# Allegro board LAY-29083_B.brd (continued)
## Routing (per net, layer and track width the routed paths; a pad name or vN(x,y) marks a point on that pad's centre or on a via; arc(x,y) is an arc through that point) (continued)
MS1_LM1: length 316.8
  TOP w0.254: U9.47 v1(31.02,26.16) ; v1(37.86,26.67) 37.85,26.66 U9.15 ; U9.39 v1(31.02,30.16) ; U8.15 v1(62.33,26.74) ; U8.30 v1(58.32,32.7) ; U9.31 v1(33.36,32.62) ; U9.30 v1(33.86,31) ; U5.8 49.57,62.48 v1(49.82,62.74) ; v1(44.65,63.89) 44.91,63.64 U5.16 ; U8.39 v1(55.48,30.24) ; U8.47 v1(55.48,26.24) ; U8.31 v1(57.82,31.07)
  TOP w0.33: U6.4 v1(24.87,43.86)
  TOP w0.432: R32.2 v1(33.34,45.95)
  TOP w0.457: C18.2 v2(47.77,47.52) ; C17.2 v2(46.76,47.52) ; C10.2 v1(53.41,52.55)
  TOP w0.508: D17.A 75.23,29.75 v1(75.72,30.24) ; D17.A v1(73.18,29.75) ; D17.A v1(74.32,28.6) ; J5.A26 v1(59.5,74.57) ; v1(22.55,49) SW7.2 v1(24.12,50.41) ; J5.C49 v1(53.5,6.12) ; J5.A49 v1(36.5,74.57) ; C12.2 v2(50.57,49.56) ; J5.C6 v1(8.5,6.12) ; D20.A v1(15.77,16.03) ; D20.A v1(14.63,14.76) ; D20.A v1(13.48,16.03) ; C28.2 v1(16.71,28.44) ; C11.2 v2(50.57,50.57) ; C26.2 v1(66.07,25.83) ; C26.2 v1(68.45,25.83) ; C26.2 v1(67.26,23.65) ; Y5.4 27.03,32.69 26.52,33.2 v1(26.44,33.2) C23.2 25.65,33.33 25.06,33.92 24.34,33.92 23.43,33.01 23.43,29.41 24.53,28.3 v1(24.53,26.66) Y5.2 24.53,24.8 C29.2 ; C7.2 42.2,55.23 42.23,55.3 42.27,55.36 v1(42.55,55.64) ; J5.C5 v1(7.5,6.12) ; v1(36.82,56.07) SW6.2 v1(38.12,54.64) ; SW5.2 v1(71.44,62.64) ; J5.A65 v1(20.5,74.45) ; D11.A v1(15.64,50.82) ; D11.A v1(14.37,49.68) ; D11.A v1(13.36,50.82) ; v2(50.57,51.33) 50.82,51.59 C9.2 ; v1(73.43,64.42) D8.A v1(74.57,65.56) ; J5.C2 v1(4.5,6.12) ; D7.C v1(66.01,66.84) ; C14.2 v2(50.57,46.76) ; J5.A5 v1(82.5,74.57) ; C8.2 v1(73.23,52.26) ; C13.2 v2(50.57,47.78) ; R49.1 v1(27.77,20.5) ; U7.3 v1(5.29,39.93) ; C27.2 v1(41.48,25.73) ; C27.2 v1(43.87,25.73) ; C27.2 v1(42.67,23.55) ; J5.A31 v1(54.5,74.57) ; C25.2 v1(39.2,29.13) ; C16.2 45.74,47.14 46.12,47.52 v2(46.76,47.52) ; v1(85.5,6.12) J5.D81 ; v1(53.62,46) C15.1 ; R47.1 v1(52.24,20.57) ; C6.2 v1(16.71,62.98) ; C24.2 v1(63.82,29.21) ; J5.A2 v1(85.5,74.57) ; J5.C31 v1(35.5,6.12) ; C30.2 v1(73.23,17.59) ; J5.C26 v1(30.5,6.12) ; SW8.2 v1(39.77,48.79) ; C5.2 v1(62.43,64.38) ; J5.C65 v1(69.5,6.12) ; D5.C v1(66.01,68.83) D6.C ; J5.A6 v1(81.5,74.57) ; J5.B81 v1(4.5,74.57)
  L5_GND w0.381: 64.92,17.78 JP7.1 ; JP7.1 66.8,17.78 ; JP7.1 65.86,16.84 ; JP7.1 65.86,18.72 ; J24.3 83.22,26.81 ; J24.3 82.11,27.92 ; J24.3 82.11,25.71 ; J24.3 81,26.81 ; J17.2 82.29,41.07 ; J17.2 81.29,39.56 ; J17.2 82.29,38.04 ; J17.2 83.3,39.56 ; J11.3 8.94,53.75 ; J11.3 7.83,54.86 ; J11.3 7.83,52.65 ; J11.3 6.73,53.75 ; 82.11,59.56 J9.4 ; J9.4 83.21,60.67 ; J9.4 84.32,59.56 ; J9.4 83.21,58.46 ; J16.3 34.67,48.51 ; J16.3 34.67,46.63 ; J16.3 33.73,47.57 ; J16.3 35.61,47.57 ; JP9.1 69.67,12.5 ; JP9.1 70.74,11.43 ; JP9.1 68.6,11.43 ; JP9.1 69.67,10.36 ; 7.83,18.11 J23.3 ; J23.3 8.94,19.21 ; J23.3 6.73,19.21 ; J23.3 7.83,20.32 ; 82.12,10.69 JP11.1 ; JP11.1 84.15,10.69 ; JP11.1 83.13,11.71 ; JP11.1 83.13,9.68 ; J17.3 79.29,45.26 ; J17.3 80.8,44.26 ; J17.3 77.78,44.26 ; J17.3 79.29,43.25 ; 45.21,10.29 JP10.1 ; JP10.1 45.21,12.42 ; JP10.1 44.14,11.35 ; JP10.1 46.28,11.35 ; JP8.1 41.4,18.64 ; JP8.1 42.34,17.7 ; JP8.1 41.4,16.76 ; JP8.1 40.46,17.7 ; 49.63,39.7 J53.3 49.63,39.02 ; JP5.1 80.41,69.88 ; JP5.1 79.4,68.86 ; JP5.1 79.4,70.89 ; JP5.1 78.38,69.88 ; J10.3 83.22,61.49 ; J10.3 81,61.49 ; J10.3 82.11,60.38 ; J10.3 82.11,62.59 ; JP6.1 58.67,57.3 ; JP6.1 56.79,57.3 ; JP6.1 57.73,56.36 ; JP6.1 57.73,58.24 ; 78.13,22.02 J22.5 ; J22.5 77.03,23.12 ; J22.5 78.13,24.23 ; J22.5 79.24,23.12 ; 66.14,53.37 J15.5 66.14,54.05 ; 49.63,38.43 J53.5 49.63,37.75 ; J22.4 83.21,26 ; J22.4 84.32,24.89 ; J22.4 83.21,23.79 ; J22.4 82.11,24.89 ; TP13.1 21.65,38.14 ; TP13.1 20.32,39.47 ; TP13.1 20.32,36.8 ; TP13.1 18.98,38.14 ; J25.4 7.83,21.13 ; J25.4 6.73,22.24 ; J25.4 5.62,21.13 ; J25.4 6.73,20.03 ; 66.14,52.78 J15.3 66.14,52.1 ; J25.5 12.91,22.9 ; J25.5 11.81,21.8 ; J25.5 10.7,22.9 ; J25.5 11.81,24.01 ; J12.5 11.81,58.55 ; J12.5 12.91,57.45 ; J12.5 11.81,56.34 ; J12.5 10.7,57.45 ; J9.5 78.13,58.9 ; J9.5 77.03,57.79 ; J9.5 78.13,56.69 ; J9.5 79.24,57.79 ; 6.73,54.57 J12.4 ; J12.4 5.62,55.68 ; J12.4 7.83,55.68 ; J12.4 6.73,56.78
  BOTTOM w0.254: U52.B2 v1(72.54,15.39) ; C65.2 62.09,26.97 v1(62.33,26.74) 62.34,26.75 C67.2 ; v2(46.76,47.52) 46.67,47.43 U50.23 ; U50.2 50.6,51.3 v2(50.57,51.33) ; U50.11 52.82,46.8 v1(53.11,46.51) 52.9,46.3 U50.12 ; C66.2 v1(37.86,26.67) C68.2 ; U53.B2 v1(73.18,11.61)
  BOTTOM w0.432: C52.2 v1(49.82,62.74) C53.2 ; C57.2 C56.2 v1(26.26,45.94) ; C50.2 v1(44.65,63.89) C51.2
  BOTTOM w0.457: C15.1 53.87,46.25 v1(53.62,46) 53.62,45.75 TP82.1
  BOTTOM w0.508: J5.C26 v1(30.5,6.12) ; D50.A 20.09,33.96 v1(20.09,31.9) ; D50.A v1(22.37,34.04) ; D50.A v1(20.01,35.84) ; J5.A2 v1(85.5,74.57) ; Y50.4 v1(43.02,43.48) ; C57.2 v1(26.26,43.46) ; J5.C5 v1(7.5,6.12) ; C75.2 v1(78.21,19.71) ; C59.2 44.7,43.74 v1(44.47,43.97) ; U51.1 v1(70.9,27.47) ; U51.1 v1(69.83,25.9) ; U51.1 v1(70.9,24.3) ; L51.2 v1(10.73,33.05) ; C61.2 v1(77.86,30.24) ; C61.2 v1(75.72,30.24) ; C61.2 v1(76.83,31.11) ; J5.C65 v1(69.5,6.12) ; J5.C31 v1(35.5,6.12) ; J5.C49 v1(53.5,6.12) ; J5.A49 v1(36.5,74.57) ; C58.2 v1(37.47,42.84) ; C71.2 v1(36.73,22.52) ; J5.A31 v1(54.5,74.57) ; v1(37.77,41.94) 38.87,41.94 Y50.2 ; J5.A6 v1(81.5,74.57) ; J5.C81 v1(85.5,6.12) ; J5.A81 v1(4.5,74.57) ; Q50.2 v1(73.79,13.75) ; J5.A5 v1(82.5,74.57) ; J5.C2 v1(4.5,6.12) ; J5.A26 v1(59.5,74.57) ; v1(23.7,42.74) R61.2 R57.2 R54.2 ; C54.2 v1(41.19,49.63) ; C70.2 v1(61.19,22.59) ; J5.C6 v1(8.5,6.12) ; J52.5 v1(6.23,41.88) ; C60.2 v1(15.04,39.4) ; J5.A65 v1(20.5,74.45)
  vias: v2(32.21,29.74) v2(32.21,28.98) v2(32.21,27.84) v2(32.21,27.08) v2(32.97,29.74) v2(32.97,28.98) v2(32.97,27.84) v2(32.97,27.08) v2(34.11,29.74) v2(34.11,28.98) v2(34.11,27.84) v2(34.11,27.08) v2(34.87,29.74) v2(34.87,28.98) v2(34.87,27.84) v2(34.87,27.08) v2(45.03,61.29) v2(45.03,60.17) v2(46.1,62.36) v2(46.1,61.29) v2(46.1,60.17) v2(46.1,59.11) v2(47.22,62.36) v2(47.22,61.29) v2(47.22,60.17) v2(47.22,59.13) v2(48.26,61.29) v2(48.26,60.17) v2(48.92,49.05) v2(56.67,29.82) v2(56.67,29.06) v2(56.67,27.91) v2(56.67,27.15) v2(57.43,29.82) v2(57.43,29.06) v2(57.43,27.91) v2(57.43,27.15) v2(58.57,29.82) v2(58.57,29.06) v2(58.57,27.91) v2(58.57,27.15) v2(59.33,29.82) v2(59.33,29.06) v2(59.33,27.91) v2(59.33,27.15)
MS1_LP1: length 40.1
  TOP w0.254: U9.35 v1(31.36,32.62)
  TOP w0.381: 9.27,60.32 J12.2 10.37,59.22 ; J11.1 7.83,62.48 ; J11.1 6.73,61.37 ; J11.1 7.83,60.27 ; J11.1 8.94,61.37
  L3_INT_1 w0.508: v1(31.36,32.62) 30.37,32.62 17.91,45.09 17.91,51.23 15.72,53.41 15.72,55.4 v1(17.71,57.39)
MS1_LP2: length 28.4
  TOP w0.254: U9.26 v1(35.86,32.62)
  TOP w0.381: 10.37,24.67 J25.2 9.27,25.78 ; J23.1 7.83,27.94 ; J23.1 8.94,26.83 ; J23.1 7.83,25.73 ; J23.1 6.73,26.83
  L4_INT_2 w0.508: v1(35.86,32.62) 35.2,33.28 29.93,33.28 22.71,26.06 v1(18.21,26.06)
MS1_MISO: length 52.3
  TOP w0.127: U9.10 v1(35.36,24.2) ; v1(46.76,56.16) 46.41,56.51 U5.28
  L3_INT_1 w0.127: v1(46.76,56.16) 46.21,55.61 45.21,55.61 45.03,55.44 43.54,55.44 42.9,56.09 40.47,56.09 39.84,55.46 39.84,54.23 39.87,54.21 39.87,49.52 39.33,48.98 39.33,48.61 39.41,48.53 39.41,32.05 37.3,29.93 37.3,25.62 36.6,24.92 36.08,24.92 v1(35.36,24.2) 35.43,24.12 35.43,21.13 JP8.2
MS1_MOSI: length 51.4
  TOP w0.127: v1(45.74,56.54) 45.91,56.71 U5.27 ; U9.9 v1(34.86,23.37)
  L3_INT_1 w0.127: JP8.3 34.86,19.17 v1(34.86,23.37) 34.86,24.33 35.97,25.44 36.49,25.44 36.97,25.91 36.97,30.24 39.13,32.4 39.13,48.41 39.05,48.49 39.05,49.09 39.59,49.63 39.59,54.09 39.56,54.12 39.56,55.58 40.35,56.36 43.12,56.36 43.77,55.72 44.92,55.72 45.09,55.89 v1(45.74,56.54)
MS1_RXD1: length 16.1
  TOP w0.127: U9.1 v1(30.86,23.37)
  L3_INT_1 w0.127: v1(30.86,23.37) 30.86,22.95 24.89,16.99 JP10.9
MS1_RXD2: length 19.7
  TOP w0.127: v1(39.29,26.21) 38.35,27.16 U9.16
  L3_INT_1 w0.127: JP10.5 39.84,16.14 39.84,25.67 v1(39.29,26.21)
MS1_SCLK: length 49.9
  TOP w0.127: U5.26 45.41,56.97 44.6,56.16 v1(44.22,56.16) ; U9.8 v1(34.36,24.2)
  L3_INT_1 w0.127: v1(44.22,56.16) 43.73,56.64 40.23,56.64 39.28,55.69 39.28,54 39.31,53.98 39.31,49.75 38.77,49.21 38.77,48.38 38.85,48.3 38.85,32.63 36.69,30.47 36.69,26.03 36.38,25.72 35.85,25.72 34.36,24.22 v1(34.36,24.2) 34.36,19.96 33.78,19.38 JP8.4
MS1_SDX1: length 66.2
  TOP w0.127: U9.4 v1(32.36,24.2) ; U5.1 v1(49.82,58.98)
  L3_INT_1 w0.127: v1(38.3,53.56) 36.21,51.46 36.21,38.25 35.08,37.11 35.08,34.29 35.3,34.06 35.3,31.65 33.41,29.76 33.41,26.89 32.36,25.84 v1(32.36,24.2) 32.36,22.99 27.72,18.35 27.72,16.14 JP10.6
  L4_INT_2 w0.127: v1(49.82,58.98) 49.5,58.66 45.38,58.66 44.39,59.65 43.27,59.65 40.92,57.3 40.92,55.14 39.34,53.56 v1(38.3,53.56)
MS1_SDX2: length 63.9
  TOP w0.127: v1(40.92,28.63) 38.73,28.63 38.7,28.6 38.26,28.6 38.2,28.66 U9.19 ; U5.2 v1(50.19,59.48)
  L3_INT_1 w0.127: JP10.2 42.67,22.92 40.92,24.67 v1(40.92,28.63) 40.92,36.93 41.8,37.82 41.8,52.86 40.28,54.38 v1(40.28,55.27)
  L4_INT_2 w0.127: v1(50.19,59.48) 49.69,59.48 49.46,59.72 44.73,59.72 44.34,60.1 43.32,60.1 40.28,57.06 v1(40.28,55.27)
MS1_SEN1: length 13.6
  TOP w0.254: 37.8,30.71 37.75,30.66 U9.23
  TOP w0.508: J21.1 R43.2 C22.2 40.61,33.53 37.8,30.71
  L4_INT_2 w0.381: J21.1 41.55,38.56 ; J21.1 40.61,39.5 ; J21.1 39.67,38.56 ; J21.1 40.61,37.62
  vias: v1(20.99,58.57) v1(21.04,57.91) v1(20.98,57.28)
MS1_SEN2: length 11.3
  TOP w0.254: U9.24 37.01,31.29
  TOP w0.508: 37.01,31.29 37.01,32.16 37.31,32.46 C21.2 R42.2 J20.1
  L4_INT_2 w0.381: 36.37,38.56 J20.1 ; J20.1 38.25,38.56 ; J20.1 37.31,37.62 ; J20.1 37.31,39.5
  vias: v1(19.66,28.02) v1(20.35,27.85) v1(20.9,28.22)
MS1_SSX: length 50.4
  TOP w0.127: U5.25 44.91,57.61 44.6,57.3 v1(44.22,57.3) ; U9.7 v1(33.86,23.37)
  L3_INT_1 w0.127: v1(44.22,57.3) 40.5,57.3 39,55.81 39,53.89 39.03,53.86 39.03,49.94 38.49,49.4 38.49,48.26 38.57,48.18 38.57,33.11 35.75,30.29 35.75,26.22 33.86,24.33 v1(33.86,23.37) 33.86,20.32 JP8.5
MS1_SSX1: length 3.7
  TOP w0.127: TP9.1 41.78,58.6 43.68,58.6 44.06,58.98 U5.24
MS1_TEMP: length 3.4
  TOP w0.127: TP21.1 29.16,26.29 29.53,26.66 U9.46
MS1_TXD1: length 20.6
  TOP w0.127: U9.2 v1(31.36,24.2)
  L3_INT_1 w0.127: v1(31.36,24.2) 31.36,23.06 26.33,18.03 26.33,10.9 26.97,10.25 28.87,10.25 JP10.7
MS1_TXD2: length 18.5
  TOP w0.127: U9.17 v1(37.82,27.66)
  L3_INT_1 w0.127: v1(37.82,27.66) 38.47,27.66 40.13,26 JP10.3
MS1_TXEN1: length 15.5
  TOP w0.127: U9.3 v1(31.86,23.37)
  L3_INT_1 w0.127: JP10.8 27.43,18.74 31.86,23.16 v1(31.86,23.37)
MS1_TXEN2: length 24.3
  TOP w0.127: U9.18 38.65,28.16 v1(38.99,27.82)
  L3_INT_1 w0.127: v1(38.99,27.82) 40.42,26.38 40.42,15.86 41.24,15.05 41.24,10.9 40.59,10.25 38.7,10.25 JP10.4
MS2_CQ1: length 53.8
  TOP w0.254: U8.33 v1(56.82,32.7)
  TOP w0.508: v1(73.3,61.62) D8.C D9.A 78.17,59.72 79.34,58.55 79.34,58.47 80.13,57.68 J10.2 J9.3
  L4_INT_2 w0.508: v1(73.3,61.62) 67.15,55.47 67.15,50.3 65.49,48.64 64.56,48.64 55.16,39.24 55.16,32.43 55.54,32.04 56.16,32.04 v1(56.82,32.7)
MS2_CQ2: length 31.6
  TOP w0.254: U8.28 v1(59.32,32.7)
  TOP w0.508: v1(73.43,27.85) 74.32,26.96 D17.C D18.A 78.35,25.05 79.34,24.06 79.34,23.8 80.13,23 J24.2 J22.3
  L4_INT_2 w0.508: v1(59.32,32.7) 59.32,32.78 60.09,33.55 61.74,33.55 66.32,28.98 72.3,28.98 v1(73.43,27.85)
MS2_GATE1: length 28.7
  TOP w0.127: v1(61.62,43.33) 61.62,45.37 64.54,48.29 66.12,48.29 R31.2 ; v1(57.68,39.4) 55.45,37.17 TP14.1 53.92,33.76 53.92,31.17 54.35,30.74 U8.38
  L4_INT_2 w0.127: v1(57.68,39.4) v1(61.62,43.33)
MS2_GATE2: length 28.1
  TOP w0.127: U8.37 v1(54.67,31.9) 54.67,32.49 54.81,32.64 TP17.1 ; R68.2 v1(68.57,16.92)
  BOTTOM w0.127: v1(54.67,31.9) 54.67,23.97 57,21.64 63.84,21.64 v1(68.57,16.92)
MS2_INTX: length 57.4
  TOP w0.127: U5.12 46.91,63.77 47.11,63.97 47.11,64.26 47.32,64.46 47.32,64.59 v1(47.77,65.05) ; U8.6 v1(57.82,24.27)
  L3_INT_1 w0.127: JP7.6 53.16,18.85 57.82,23.5 v1(57.82,24.27) 57.82,25.03 56.22,26.63 56.22,31.08 57.23,32.09 57.23,32.49 57.26,32.52 57.26,32.88 57.23,32.91 57.23,43.72 54.12,46.83 54.12,48.04 52.78,49.38 52.78,49.98 48.98,53.77 48.98,63.98 47.91,65.05 v1(47.77,65.05)
MS2_LP1: length 38.3
  TOP w0.254: U8.35 v1(55.82,32.7)
  TOP w0.381: J10.1 82.11,54.97 ; J10.1 82.11,52.76 ; J10.1 83.22,53.87 ; J10.1 81,53.87 ; 80.67,54.92 J9.2 79.57,56.02
  L4_INT_2 w0.508: v1(71.88,54.58) 68.6,54.58 67.84,53.82 67.84,49.99 65.81,47.96 64.97,47.96 61.61,44.59 58.56,41.3 55.82,38.55 v1(55.82,32.7)
MS2_LP2: length 24.1
  TOP w0.254: U8.26 v1(60.32,32.7)
  TOP w0.381: J24.1 83.22,19.19 ; J24.1 81,19.19 ; J24.1 82.11,20.3 ; J24.1 82.11,18.09 ; 79.57,21.35 J22.2 80.67,20.25
  L4_INT_2 w0.508: v1(60.32,32.7) 61.23,32.7 66.7,27.23 66.7,25.88 71.09,21.49 v1(71.52,21.49)
MS2_MISO: length 55.6
  TOP w0.127: U8.10 v1(59.82,24.27) ; v1(49.55,57.68) 48.81,57.68 48.41,58.09 U5.32
  L3_INT_1 w0.127: v1(60.45,55.74) 61.05,55.14 61.05,48.98 62.75,47.28 62.75,34.49 61.11,32.85 61.11,27.48 59.82,26.19 v1(59.82,24.27) 59.82,21.28 JP7.2
  L4_INT_2 w0.127: v1(49.55,57.68) 52.85,57.68 54.8,55.74 v1(60.45,55.74)
MS2_MOSI: length 53.2
  TOP w0.127: v1(49.53,56.41) 47.91,58.03 U5.31 ; U8.9 v1(59.32,23.45)
  L3_INT_1 w0.127: v1(60.48,53.16) 60.77,52.87 60.77,27.57 59.32,26.11 v1(59.32,23.45) 59.32,19.24 JP7.3
  L4_INT_2 w0.127: v1(49.53,56.41) 53.11,56.41 55.76,53.76 59.88,53.76 v1(60.48,53.16)
MS2_RXD1: length 16.1
  TOP w0.127: U8.1 v1(55.32,24.27)
  L3_INT_1 w0.127: JP9.9 49.35,18.32 52.05,21.02 52.06,21.02 v1(55.32,24.27)
MS2_RXD2: length 20.3
  TOP w0.127: U8.16 v1(63.78,27.24)
  L3_INT_1 w0.127: JP9.5 64.3,16.22 64.3,26.72 v1(63.78,27.24)
MS2_SCLK: length 52.4
  TOP w0.127: U8.8 v1(58.82,24.27) ; v1(47.5,57.41) 47.41,57.49 U5.30
  L3_INT_1 w0.127: JP7.4 58.82,18.36 v1(58.82,24.27) 58.82,26.01 59.78,26.97 59.78,34 59.44,34.34 59.44,36.25 60.44,37.25 60.44,52 v1(59.41,53.04)
  L4_INT_2 w0.127: v1(47.5,57.41) 49.73,55.17 53.59,55.17 55.28,53.48 58.97,53.48 v1(59.41,53.04)
MS2_SDX1: length 66.5
  TOP w0.127: U8.4 v1(56.82,23.45) ; U5.22 43.37,59.98 43.23,59.84 v1(41.93,59.84)
  L3_INT_1 w0.127: v1(41.93,59.84) 43.01,58.76 44.78,58.76 47.2,56.34 47.2,55.98 46.56,55.33 45.33,55.33 44.79,54.8 44.79,54.19 56.26,42.71 56.26,32.49 55.94,32.17 55.94,26.51 56.82,25.64 v1(56.82,23.45) 52.18,18.81 52.18,17.37 55.53,14.03 56.97,12.59 JP9.6
MS2_SDX2: length 71.5
  TOP w0.127: U5.23 43.73,59.48 v1(43.46,59.21) ; U8.19 v1(62.28,28.74)
  L3_INT_1 w0.127: v1(60.98,58.07) 61.37,57.67 61.37,50.05 63.87,47.56 63.87,33.27 61.79,31.18 61.79,29.23 v1(62.28,28.74) 63.79,28.74 66.51,26.02 66.51,23.37 67.13,22.75 JP9.2
  L4_INT_2 w0.127: v1(60.98,58.07) 60.66,58.38 44.28,58.38 v1(43.46,59.21)
MS2_SEN1: length 13.5
  TOP w0.254: 62.35,31.05 62.03,30.74 U8.23
  TOP w0.508: J19.1 R41.2 C20.2 65.07,33.78 62.35,31.05
  L4_INT_2 w0.381: J19.1 66.02,38.63 ; J19.1 64.13,38.63 ; J19.1 65.07,39.57 ; J19.1 65.07,37.69
  vias: v1(68.58,53.39) v1(68.55,52.65) v1(69.09,53)
MS2_SEN2: length 11.3
  TOP w0.254: U8.24 61.47,31.37
  TOP w0.508: J18.1 R40.2 C19.2 61.77,33.58 61.47,33.27 61.47,31.37
  L4_INT_2 w0.381: 61.77,37.69 J18.1 ; J18.1 61.77,39.57 ; J18.1 62.71,38.63 ; J18.1 60.83,38.63
  vias: v1(69.01,20.47) v1(69.02,19.79) v1(69.04,19.1)
MS2_SSX: length 54.5
  TOP w0.127: U8.7 v1(58.32,23.45) ; U5.29 v1(46.91,57.57)
  L3_INT_1 w0.127: JP7.5 58.32,20.4 v1(58.32,23.45) 58.32,26.31 58.13,26.5 58.13,30 58.26,30.14 58.26,32.02 57.87,32.41 57.87,35.19 58.31,35.62 58.31,37.16 58.2,37.26 58.2,39.89 60.16,41.85 60.16,51.39 v1(59.87,51.69)
  L4_INT_2 w0.127: v1(46.91,57.57) 46.91,57.15 49.17,54.89 53.23,54.89 54.92,53.2 58.36,53.2 v1(59.87,51.69)
MS2_TEMP: length 1.2
  TOP w0.127: U8.46 53.48,26.74 TP20.1
MS2_TXD1: length 16.3
  TOP w0.127: U8.2 v1(55.82,23.45)
  L3_INT_1 w0.127: v1(55.82,23.45) 55.82,22.99 51.9,19.08 51.9,16.27 54.43,13.74 JP9.7
MS2_TXD2: length 19
  TOP w0.127: U8.17 v1(62.28,27.74)
  L3_INT_1 w0.127: JP9.3 64.59,27.05 63.91,27.74 v1(62.28,27.74)
MS2_TXEN1: length 15.9
  TOP w0.127: U8.3 v1(56.32,24.27)
  L3_INT_1 w0.127: v1(56.32,24.27) 56.02,24.27 52.96,21.22 52.96,20.53 51.63,19.19 51.63,16.15 51.89,15.89 JP9.8
MS2_TXEN2: length 25.4
  TOP w0.127: U8.18 v1(63.11,28.24)
  L3_INT_1 w0.127: v1(63.11,28.24) 63.8,28.24 64.87,27.17 64.87,16.04 65.81,15.1 65.81,10.57 65.3,10.06 63.42,10.06 JP9.4
RST_KL25Z: length 22.2
  TOP w0.127: 46.48,42.42 R34.2 46.06,42.89 45.93,42.89 45.08,43.74 45.08,45.09 C16.1 44.69,46.8 v1(44.63,46.8) ; 46.48,42.42 46.48,41.1 45.74,40.36 45.74,36.22 46.76,35.21 47.27,35.21 ; 46.48,42.42 45.74,41.68 TP12.1 43.17,41.65 SW8.1
  BOTTOM w0.127: U50.26 v1(44.63,46.8)
RST_MCU: length 32.4
  TOP w0.127: C5.1 R26.2 ; R26.2 63.28,61.49 64.43,62.64 SW5.1 ; R26.2 60.98,61.49 TP8.1 60.98,60.66 60.5,60.17 v1(60.5,59.13) 61.06,59.13 62.51,57.68 62.51,56.77 63.37,55.91 J15.10 ; U5.19 43.37,61.48 v1(43.26,61.37)
  L4_INT_2 w0.127: v1(60.5,59.13) 60.04,59.59 55.88,59.59 55.69,59.4 51.51,59.4 50.45,60.45 49.18,60.45 48.8,60.83 44.37,60.83 43.84,61.37 v1(43.26,61.37)
SHIELD_K20USB: length 22.8
  BOTTOM w0.508: L51.1 7.75,33.21 J52.S1 J52.S3 J52.S4 J52.S2
SPI0_CLK: length 7
  TOP w0.127: J5.B48 37.5,74.81 34.69,72.01 R14.2
SPI0_CS0: length 10.9
  TOP w0.127: J5.B46 v1(39.5,74.6) ; R20.2 v1(43.65,68.92)
  L3_INT_1 w0.127: v1(39.5,74.6) 39.5,73.07 v1(43.65,68.92)
SPI0_CS1: length 6.2
  TOP w0.127: J5.B47 38.5,71.85 R16.2
SPI0_MISO: length 13.1
  TOP w0.127: J5.B44 v1(41.5,74.65) ; R13.2 v1(33.04,72.04)
  L3_INT_1 w0.127: v1(33.04,72.04) 34.18,73.18 36.09,73.18 37.95,75.04 41.1,75.04 v1(41.5,74.65)
SPI0_MOSI: length 6.2
  TOP w0.127: J5.B45 40.5,73.45 39.77,72.72 R17.2
SPI1_CLK: length 57
  TOP w0.127: J5.B7 v1(80.5,74.62)
  L4_INT_2 w0.127: J7.4 35.45,65.99 35.45,68.61 38.25,71.4 71.54,71.4 72.63,70.31 75.85,70.31 76.31,70.31 76.31,70.31 76.65,70.31 78.05,71.71 78.05,73.72 78.45,74.12 80,74.12 v1(80.5,74.62)
SPI1_CS0: length 47.4
  TOP w0.127: v1(78.5,73.53) J5.B9
  L4_INT_2 w0.127: J8.4 46,70.51 72.03,70.51 72.51,70.03 75.74,70.03 76.43,70.03 76.43,70.03 76.77,70.03 78.5,71.76 v1(78.5,73.53)
SPI1_CS1: length 44.4
  TOP w0.127: R18.2 v1(41.61,72) ; J5.B8 v1(79.5,74.58)
  L4_INT_2 w0.127: v1(79.5,74.58) 78.52,74.58 77.77,73.83 77.77,72.16 76.2,70.59 75.97,70.59 72.74,70.59 71.65,71.68 71.65,71.68 71.34,72 v1(41.61,72)
SPI1_MISO: length 59.5
  TOP w0.127: v1(76.6,74.45) 76.5,74.55 J5.B11
  L4_INT_2 w0.127: J6.4 29.74,66.27 29.74,67.35 35.11,72.72 71.4,72.72 72.98,71.15 75.97,71.15 76.98,72.16 76.98,74.07 v1(76.6,74.45)
SPI1_MOSI: length 69.7
  TOP w0.127: J5.B10 v1(77.5,74.45)
  L4_INT_2 w0.127: v1(77.5,74.45) 77.5,73.95 77.49,73.95 77.49,72.28 76.08,70.87 72.86,70.87 71.29,72.44 37.76,72.44 34.82,69.5 32.28,69.5 30.12,67.34 30.12,57.81 30.88,57.05 32.53,57.05 J14.4
SPI2_CLK: length 89.5
  TOP w0.127: R15.2 v1(36.22,72.04) ; J5.D7 v1(9.5,6.12)
  L3_INT_1 w0.127: v1(9.5,6.12) 9.95,6.58 9.95,18.83 13.93,22.81 13.93,50.24 14.08,50.39 14.08,65.39 19.46,70.77 34.95,70.77 v1(36.22,72.04)
SPI2_CS0: length 95.7
  TOP w0.127: R24.2 v1(44.47,65.56) ; J5.D9 v1(11.5,6.12)
  L3_INT_1 w0.127: v1(23.17,58.49) 22.34,58.49 21.81,59.02 18.28,59.02 14.92,55.65 14.92,50.16 15.49,49.59 15.49,39.21 15.13,38.86 15.13,16.89 11.5,13.25 v1(11.5,6.12)
  BOTTOM w0.127: v1(23.17,58.49) 24.41,59.72 27.61,59.72 29.61,61.71 29.61,67.21 31.58,69.18 39.96,69.18 43.58,65.56 v1(44.47,65.56)
SPI2_CS1: length 95.9
  TOP w0.127: v1(10.5,6.12) J5.D8 ; R22.2 v1(44.98,66.19)
  L3_INT_1 w0.127: v1(10.5,6.12) 10.5,18.19 14.6,22.29 14.6,49.28 14.82,49.5 14.82,49.87 14.64,50.05 14.64,55.77 18.21,59.34 v1(22.12,59.34)
  BOTTOM w0.127: v1(44.98,66.19) 43.58,66.19 40.32,69.46 31.47,69.46 29.1,67.09 29.1,61.6 27.5,60 22.78,60 v1(22.12,59.34)
SPI2_MISO: length 89.9
  TOP w0.127: v1(13.39,6.12) 13.39,3.7 J5.D11 ; R12.2 v1(31.39,72.04)
  L3_INT_1 w0.127: v1(31.39,72.04) 30.5,71.15 19.44,71.15 13.8,65.5 13.8,50.51 13.65,50.36 13.65,22.92 9.67,18.95 9.67,14.89 9.05,14.26 9.05,5.94 9.31,5.68 12.94,5.68 v1(13.39,6.12)
SPI2_MOSI: length 85.3
  TOP w0.127: J5.D10 v1(12.5,6.12) ; R27.2 37.99,58.1 37.51,57.62 37.42,57.62 35.84,56.03 35.84,52.73 34.82,51.72 30.76,51.72 28.11,54.36 24.46,54.36 23.26,55.55 v1(23.26,56.83)
  L3_INT_1 w0.127: v1(12.5,6.12) 12.5,13.86 15.41,16.77 15.41,38.74 15.77,39.1 15.77,49.71 15.2,50.28 15.2,55.54 17.53,57.87 19.76,57.87 20.8,56.83 v1(23.26,56.83)
SWD_CLK: length 27.1
  TOP w0.127: v1(49.17,65.05) 49.17,65.05 47.91,63.79 U5.10
  L4_INT_2 w0.127: J15.4 62.43,52.1 62.1,52.43 62.1,58.55 61.74,58.9 61.74,60.83 57.53,65.05 v1(49.17,65.05)
SWD_CLK_KL25Z: length 10.8
  L4_INT_2 w0.127: v1(47.41,42.92) 47.42,42.93 v1(49.63,42.93)
  BOTTOM w0.127: v1(47.41,42.92) 46.86,42.37 46.86,41.5 45.82,40.46 45.82,39.47 46.27,39.02 J53.4 ; U50.17 49.67,45 49.77,44.9 49.77,43.07 v1(49.63,42.93)
SWD_DIO: length 29.9
  TOP w0.127: U5.13 46.41,63.66 46.83,64.09 46.83,64.37 47.01,64.55 v1(47.01,65.05)
  L4_INT_2 w0.127: v1(47.01,65.05) 47.46,64.61 47.96,64.61 48.92,63.65 58.53,63.65 61.1,61.08 61.1,59.14 61.67,58.57 61.67,51.82 62.67,50.81 63.76,50.81 J15.2
SWD_DIO_KL25Z: length 6
  BOTTOM w0.127: J53.2 47.27,42.15 47.89,42.77 47.89,42.94 48.54,43.59 48.54,44.73 48.17,45.1 U50.20
TC_USB_ID_TP: length 2.8
  BOTTOM w0.127: J52.4 9.49,41.08 TP90.1
TWR_3V3: length 41.4
  TOP w0.508: J5.C82 86.44,3.7 86.44,6.5 v1(85.98,6.96) ; J5.A36 v1(49.5,74.57) ; J5.A82 3.51,77.02 3.51,74.4 v1(4.06,73.84) ; J5.C36 v1(40.5,6.12) ; J5.C3 v1(5.5,6.12) ; J5.A3 v1(84.5,74.57)
  BOTTOM w0.254: R66.1 75.05,12.37 U53.A1 U53.B1
  BOTTOM w0.508: J5.C4 v1(6.5,6.12) ; J5.C82 86.44,3.7 86.44,6.5 v1(85.98,6.96) ; J5.C36 v1(40.5,6.12) ; J5.A36 v1(49.5,74.57) ; J5.A3 v1(84.5,74.57) ; J5.A82 3.51,77.02 3.51,74.4 v1(4.06,73.84) ; J5.A4 v1(83.5,74.57) ; J5.C3 v1(5.5,6.12) ; R66.1 v1(75.06,11.39)
TWR_CLK: length 45.7
  TOP w0.127: J7.1 J7.3 J7.5 ; U5.4 v1(51.74,60.48)
  L3_INT_1 w0.127: v1(51.74,60.48) 51.74,55.75 54.29,53.2 54.29,50.59 JP6.5
  L4_INT_2 w0.127: J7.5 32.57,63.11 47.56,63.11 49.55,61.11 51.06,61.11 51.69,60.48 v1(51.74,60.48)
TWR_CS0: length 45.7
  TOP w0.127: U5.3 v1(49.82,59.98) ; J8.1 J8.3 J8.5
  L3_INT_1 w0.127: JP6.6 58.71,45.58 58.71,58.75 v1(58.34,59.12)
  L4_INT_2 w0.127: v1(58.34,59.12) 51.18,59.12 50.32,59.98 v1(49.82,59.98)
  BOTTOM w0.127: J8.5 38.31,62.83 42.42,62.83 44.53,60.72 44.53,59.65 45.52,58.66 48.5,58.66 v1(49.82,59.98)
TWR_INT: length 56.1
  TOP w0.127: U5.9 48.41,63.35 49.35,64.29 v1(50.39,64.29)
  L3_INT_1 w0.127: J13.1 J13.3 J13.5 ; v1(50.39,64.29) 53.74,60.94 53.74,58.75 JP6.2
  BOTTOM w0.127: v1(50.39,64.29) 48.52,64.29 46.77,62.54 46.77,62.15 46.54,61.91 44.31,61.91 43.11,63.11 33.62,63.11 32.73,62.21 32.73,61.18 34.98,58.92 34.98,57.76 34.15,56.92 26.44,56.92 J13.1
TWR_INT_1: length 1.8
  TOP w0.127: R8.1 R7.2
TWR_INT_2: length 14.9
  TOP w0.127: R9.1 25.48,68.81 26.56,67.72 26.56,56.8 J13.4
TWR_INT_3: length 9.5
  TOP w0.127: R10.1 v1(27.51,68.77) ; 19.83,69.62 R6.2 v1(19.83,68.66)
  L3_INT_1 w0.127: v1(19.83,68.66) 27.39,68.66 v1(27.51,68.77)
TWR_INT_4: length 13.7
  TOP w0.127: v1(18.06,68.73) R5.2 18.06,69.62 ; R11.1 v1(29.54,68.77)
  L3_INT_1 w0.127: v1(18.06,68.73) 18.69,69.37 28.94,69.37 v1(29.54,68.77)
TWR_MISO: length 52.5
  TOP w0.127: J6.5 J6.3 J6.1 ; v1(51.74,61.62) 51.4,61.28 49.64,61.28 49.43,61.48 U5.6
  L3_INT_1 w0.127: JP6.3 53.11,56.85 53.11,60.25 v1(51.74,61.62)
  BOTTOM w0.127: v1(51.74,61.62) 51.74,64.39 48.03,68.1 42.07,68.1 40.43,69.74 29.35,69.74 27.83,68.23 26.62,68.23 J6.1
TWR_MOSI: length 47.4
  TOP w0.127: v1(52.4,59.84) 52.4,60.6 52.02,60.98 U5.5 ; J14.1 J14.3 J14.5
  L3_INT_1 w0.127: v1(52.4,59.84) 52.4,55.85 54.57,53.68 54.57,52.85 JP6.4
  L4_INT_2 w0.127: J14.1 32.53,59.34 32.53,62.02 33.34,62.83 43.14,62.83 44.15,61.81 48.37,61.81 49.45,60.73 50.57,60.73 51.46,59.84 52.4,59.84 v1(52.4,59.84)
USB_CONN_DN: length 5
  TOP w0.108: v1(9.46,39.5) 9.14,39.82 8.41,39.82 8.3,39.71 U7.1
  BOTTOM w0.108: J52.2 9.44,39.48 v1(9.46,39.5) 9.77,39.82 10.17,39.82 10.47,39.52 R64.1
USB_CONN_DP: length 5.1
  TOP w0.108: v1(9.46,40.36) 9.14,40.04 8.41,40.04 8.3,40.15 U7.2
  BOTTOM w0.108: R63.1 10.47,40.29 10.23,40.04 9.77,40.04 v1(9.46,40.36) 9.38,40.28 J52.3
USB_DM: length 52.8
  L4_INT_2 w0.108: v1(37.77,47.24) 37.45,47.56 37.45,48.13 37.74,48.41 39.14,48.41 41.55,46 51.2,46 52.03,46.83 52.03,50 52.47,50.45 53.09,50.45 v1(53.23,50.3)
  BOTTOM w0.108: v1(53.23,50.3) U50.4 ; v1(37.77,47.24) 37.45,46.93 37.45,46.04 35.04,43.62 33.01,43.62 30.97,41.59 26.4,41.59 25.64,40.83 14.34,40.83 13.33,39.82 11.6,39.82 11.49,39.71 R64.2
USB_DP: length 53
  L4_INT_2 w0.108: v1(53.23,50.96) 53.21,50.96 52.92,50.67 52.38,50.67 51.81,50.09 51.81,46.92 51.11,46.22 41.64,46.22 39.23,48.64 37.65,48.64 37.23,48.22 37.23,47.56 v1(36.92,47.24)
  BOTTOM w0.108: R63.2 11.49,40.15 11.6,40.04 13.24,40.04 14.25,41.05 25.55,41.05 26.31,41.81 30.88,41.81 32.91,43.84 34.95,43.84 37.23,46.13 37.23,46.93 v1(36.92,47.24) ; v1(53.23,50.96) 53.23,50.91 53.13,50.8 U50.3
VREFH: length 6.9
  TOP w0.61: v1(56.16,47.27) C15.2
  BOTTOM w0.254: U50.10 52.95,47.3 53.05,47.2 53.11,47.2 53.17,47.14 54.25,47.14 C15.2
  BOTTOM w0.61: R53.1 55.39,48.29 TP80.1 ; R53.1 v1(56.16,47.27) ; R53.1 C15.2
N51941022: length 4.2
  TOP w0.127: v1(27.91,43.71) 28.3,43.71 28.44,43.86 U6.5 30.16,43.86 R35.1
  BOTTOM w0.127: R60.2 v1(27.91,43.71)
N51941025: length 3.8
  TOP w0.127: v1(27.91,44.65) 28.3,44.65 28.44,44.51 U6.6 30.96,44.51 R33.1
  BOTTOM w0.127: R59.2 v1(27.91,44.65)
N51968614: length 8
  TOP w0.127: U9.41 29.34,29.16 28.34,30.16 28.34,33.46 27.18,34.62 D15.C
N51968623: length 6.7
  TOP w0.127: U9.40 29.27,29.66 29.08,29.84 D16.C
N51972698: length 9.4
  TOP w0.127: U9.44 29.59,27.66 29.49,27.76 25.89,27.76 25.76,27.63 25.76,26.8 27.03,25.52 Y5.3 27.03,25.14 C29.1
N51980032: length 2.1
  TOP w0.127: R32.1 30.17,45.16 U6.7
N51981285: length 1.2
  TOP w0.127: R23.1 D7.A
N51981437: length 1.2
  TOP w0.127: R21.2 D6.A
N51981716: length 1.2
  TOP w0.127: D16.A R39.1
N51981719: length 1.2
  TOP w0.127: D15.A R38.1
N51986239: length 5.1
  TOP w0.127: U9.48 30.2,25.65 R67.1 R49.2
N52006957: length 12.8
  TOP w0.127: R18.1 42.13,69.1 R20.1 42.13,67.85 R22.1 R24.1 41.42,64.42 40.79,65.05 40.79,65.86 J8.2 37.8,68.86 R16.1
N52007703: length 5.9
  TOP w0.127: J5.B60 25.5,71.17 R9.2
N52007706: length 5.9
  TOP w0.127: R8.2 23.5,71.2 J5.B62
N52011483: length 5.1
  TOP w0.127: U8.48 54.66,25.73 R48.1 R47.2
N52011777: length 8.2
  TOP w0.127: U8.41 53.34,29.24 51.64,30.94 D13.C
N52011781: length 6.5
  TOP w0.127: D14.C 53.54,30.35 54.16,29.74 U8.40
N52011843: length 1.2
  TOP w0.127: R37.1 D14.A
N52011845: length 1.2
  TOP w0.127: R36.1 D13.A
N52039256: length 5.9
  TOP w0.127: R11.2 29.5,71.19 J5.B56
N52039259: length 5.9
  TOP w0.127: J5.B58 27.5,71.16 R10.2
N52039370: length 21.6
  TOP w0.127: R5.1 R6.1 R7.1 v1(21.61,72)
  L4_INT_2 w0.127: J13.2 25.55,60.35 24.15,60.35 22.63,61.88 22.63,70.98 v1(21.61,72)
N52105751: length 3.7
  BOTTOM w0.127: R65.2 Q50.3 75.63,15.75 U52.B1
N52105774: length 1.4
  BOTTOM w0.127: R66.2 Q50.1
N52116188: length 10.2
  TOP w0.127: U9.43 29.61,28.16 29.49,28.04 25.81,28.04 25.1,28.75 25.1,30.78 Y5.1 24.64,31.45 C23.1
N52149421: length 6.9
  TOP w0.127: TP22.1 v1(11.25,15.8)
  BOTTOM w0.127: v1(11.25,15.8) 11.25,19.15 J25.1
N52149434: length 6.9
  TOP w0.127: v1(11.25,50.34) TP10.1
  BOTTOM w0.127: J12.1 11.25,53.69 v1(11.25,50.34)
N52149447: length 6.9
  TOP w0.127: v1(78.69,30.23) TP19.1
  BOTTOM w0.127: v1(78.69,30.23) 78.69,26.88 J22.1
N52149460: length 6.9
  TOP w0.127: TP5.1 v1(78.69,64.9)
  BOTTOM w0.127: J9.1 78.69,61.55 v1(78.69,64.9)
N52159106: length 2
  TOP w0.127: Q6.3 70.94,53.54 R31.1
N52159127: length 2
  TOP w0.127: Q8.3 70.94,18.87 R68.1
N52159490: length 10.1
  TOP w0.381: J17.1 76.29,41.07 ; J17.1 77.3,39.56 ; J17.1 76.29,38.04 ; J17.1 75.29,39.56
  BOTTOM w0.381: J17.1 76.29,41.07 ; J17.1 77.3,39.56 ; J17.1 76.29,38.04 ; J17.1 75.29,39.56
  vias: v1(71.41,45.75) v1(71.41,44.48) v1(71.41,42.95) v1(72.47,46.41) v1(72.47,42.29) v1(73.61,46.41) v1(73.74,42.29) v1(74.74,45.75) v1(74.74,44.35) v1(74.74,42.95)
N52178619: length 2
  TOP w0.127: R44.1 18.98,29.09 Q7.3
N52178906: length 2
  TOP w0.127: R25.1 18.98,63.64 Q5.3
N52281250: length 6.4
  TOP w0.127: R13.1 R12.1 29.61,67.84 28.78,67.84 J6.2
N52284736: length 6.1
  BOTTOM w0.508: F50.2 14.93,37.73 L50.1 14.98,34.64 D50.C
N52285941: length 13.6
  BOTTOM w0.127: C59.1 44.7,42.18 Y50.1 42.83,42.18 41.17,43.84 41.17,45.78 41.36,45.97 41.36,46.06 R56.1 41.42,46.89 41.42,47.25 41.55,47.37 42.32,47.37 43.97,45.72 45.13,45.72 45.2,45.65 U50.24
N52286024: length 13.5
  BOTTOM w0.127: U50.25 45.02,46.3 44.73,46 44.09,46 42.44,47.65 41.3,47.65 40.28,46.64 R56.2 40.28,46.38 40.89,45.77 40.89,43.69 40.79,43.59 40.28,43.59 39.28,44.58 Y50.3 37.47,44.58 C58.1
N52286041: length 3.4
  BOTTOM w0.127: R51.1 51.33,54.64 49.67,52.97 U50.44
N52290882: length 2.5
  BOTTOM w0.127: U50.13 51.67,45.16 TP83.1
N52290920: length 8.6
  BOTTOM w0.127: U50.28 44.48,47.8 43.63,48.64 43.63,49.94 42.74,50.83 TP78.1
N52290933: length 7.4
  BOTTOM w0.127: U50.29 44.56,48.3 43.91,48.95 43.91,50.05 42.38,51.59 TP76.1
N52290949: length 8.7
  BOTTOM w0.127: TP75.1 42.01,52.35 44.19,50.17 44.19,49.18 44.57,48.8 U50.30
N52290962: length 7.3
  BOTTOM w0.127: U50.31 44.86,49.3 44.47,49.68 44.47,50.28 41.64,53.11 TP74.1
N52290975: length 4.7
  BOTTOM w0.127: TP73.1 42.69,52.46 44.75,50.4 44.75,50.14 45.09,49.8 U50.32
N52291034: length 6.2
  BOTTOM w0.127: TP72.1 42.82,53.87 43.66,53.04 43.66,51.89 45.25,50.3 U50.33
N52291047: length 5.2
  BOTTOM w0.127: TP67.1 42.69,54.4 44.14,52.95 44.14,51.82 45.16,50.8 U50.34
N52291060: length 3.3
  BOTTOM w0.127: TP71.1 44.62,53.34 44.62,51.92 45.25,51.3 U50.35
N52291085: length 3.6
  BOTTOM w0.127: TP66.1 44.85,53.57 45.52,52.91 U50.36
N52291099: length 1.5
  BOTTOM w0.127: U50.37 46.17,53.07 45.87,53.37 TP70.1
N52291114: length 2.7
  BOTTOM w0.127: U50.38 46.67,55.11 TP64.1
N52291127: length 1.5
  BOTTOM w0.127: TP69.1 47.17,53.65 U50.39
N52291143: length 2.9
  BOTTOM w0.127: U50.40 47.67,53.3 48.15,53.79 TP58.1
N52291156: length 2
  BOTTOM w0.127: U50.15 50.69,45.62 50.69,44.48 50.82,44.35 TP84.1
N52291179: length 2
  BOTTOM w0.127: TP68.1 48.76,54 48.17,53.41 U50.41
N52291192: length 2.9
  BOTTOM w0.127: TP57.1 49.68,53.49 49.36,53.18 49.36,53 49.17,52.81 U50.43
N52291212: length 3.6
  BOTTOM w0.127: R50.1 52.32,55.14 50.17,52.99 U50.45
N52302946: length 2.2
  TOP w0.127: U5.17 42.85,62.48 TP6.1
N52302949: length 2
  TOP w0.127: U5.18 43.18,61.98 42.95,61.75 TP7.1
N52312996: length 21.2
  TOP w0.127: R27.1 J14.2 ; 39.77,69.62 R17.1 v1(39.77,68.73)
  BOTTOM w0.127: v1(39.77,68.73) 33.68,68.73 32.45,67.5 32.45,59.68 J14.2
N52313183: length 4.7
  TOP w0.127: R14.1 34.69,67.77 J7.2 ; R14.1 R15.1 ; R14.1 34.69,69.62
N52316776: length 1.4
  TOP w0.127: R19.1 69.36,69.75 D5.A
N522864580: length 3.5
  BOTTOM w0.127: U50.7 52.75,48.8 52.87,48.68 53.55,48.68 53.88,49.01 54.59,49.01 55.27,49.69 TP79.1
N522864581: length 1.9
  BOTTOM w0.127: U50.8 54.01,48.3 TP81.1
N522864582: length 3.8
  BOTTOM w0.127: U50.14 51.17,44.77 52.22,43.71 TP87.1
N5228645815: length 1.9
  BOTTOM w0.127: TP85.1 49.17,45.64 U50.18
N5228645818: length 2
  BOTTOM w0.127: TP86.1 47.52,44.73 47.67,44.88 U50.21
N5228645847: length 3.3
  BOTTOM w0.127: U50.16 50.17,43.1 50.19,43.08 TP88.1

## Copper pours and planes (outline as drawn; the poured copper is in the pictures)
3V3 on L2_PWR: 18.36,70.38 18.36,12.34 73.61,12.34 73.61,64.29 67.51,70.38 ; 27 cut-outs
24V on TOP: 64.03,47.14 64.03,41.05 69.42,41.05 69.42,47.14
24V on BOTTOM: 32.33,41.05 45.61,41.05 45.61,34.7 46.12,34.19 49.68,34.19 51,35.51 51,43.33 59,43.33 59,68.99 71.96,68.99 71.96,66.57 70.51,66.57 70.51,26.95 32.33,26.95 ; 16 cut-outs
P3V3_KL25Z on L2_PWR: 43.07,39.78 50.44,39.78 56.54,45.87 56.54,47.85 54.5,49.89 54.5,52.48 53.74,53.24 44.09,53.24 40.36,49.51 40.36,42.5 ; 1 cut-out
MS1_LM1 on L5_GND: 13.23,1.68 3.76,1.68 3.76,10.31 3,11.07 0.71,11.07 0.71,69.49 3,69.49 3.76,70.26 3.76,78.89 73.25,78.89 73.25,73.03 75.01,71.27 76.76,73.03 76.76,78.89 86.31,78.89 86.31,70.13 86.94,69.49 89.23,69.49 89.23,11.07 86.94,11.07 86.31,10.44 86.31,7.58 86.23,1.68 16.74,1.68 16.74,7.53 14.99,9.35 13.23,7.54 ; 18 cut-outs
MS1_LP1 on TOP: 6.3,63.02 19.13,63.02 19.13,59.08 19.12,59.08 19.12,57.05 16.28,57.05 15.71,57.62 9.66,57.62 6.3,60.99
MS1_LP2 on TOP: 6.3,28.47 19.13,28.47 19.13,22.5 17.48,22.5 16.9,23.08 9.66,23.08 6.3,26.44
MS1_SEN1 on TOP: 19.27,63.02 19.27,57.05 21.29,57.05 21.29,63.02
MS1_SEN1 on L4_INT_2: 18.62,59.21 23.57,59.21 23.57,54.38 31.32,46.63 38.94,46.63 42.37,43.21 42.37,36.98 38.94,36.98 38.94,40.16 28.52,40.16 18.62,50.06
MS1_SEN2 on TOP: 19.38,28.47 19.38,22.5 21.16,22.5 21.16,28.47
MS1_SEN2 on L4_INT_2: 18.75,27.2 18.75,32.54 26.11,39.9 38.81,39.9 38.81,34.06 27.76,34.06 20.9,27.2
MS2_LP1 on TOP: 83.64,52.22 70.82,52.22 70.82,58.19 72.47,58.19 73.04,57.62 80.28,57.62 83.64,54.25
MS2_LP2 on TOP: 83.64,17.55 70.82,17.55 70.82,23.52 72.47,23.52 73.04,22.95 80.28,22.95 83.64,19.58
MS2_SEN1 on TOP: 67.92,58.19 67.92,52.22 70.61,52.22 70.61,58.19
MS2_SEN1 on L4_INT_2: 68.47,53.62 72.21,53.62 72.21,37.87 70.82,36.47 64.72,36.47 63.58,37.62 63.58,45.8 68.22,50.45 68.22,53.37
MS2_SEN2 on TOP: 68.07,23.52 68.07,17.53 70.56,17.53 70.56,23.52
MS2_SEN2 on L4_INT_2: 59.89,40.34 63.32,40.34 63.32,37.49 67.26,33.55 77.55,33.55 77.55,16.66 67.79,16.66 67.79,20.85 73.61,20.85 73.61,29.36 66.62,29.36 59.89,36.09
TWR_3V3 on L2_PWR: 13.23,1.68 3.76,1.68 3.76,10.31 3,11.07 0.71,11.07 0.71,69.49 3,69.49 3.76,70.26 3.76,78.89 73.25,78.89 73.25,73.03 75.01,71.27 76.76,73.03 76.76,78.89 86.31,78.89 86.31,70.13 86.94,69.49 89.23,69.49 89.23,11.07 86.94,11.07 86.31,10.44 86.31,7.58 86.23,1.68 16.74,1.68 16.74,7.53 14.99,9.35 13.23,7.54 ; 7 cut-outs
N52159490 on TOP, BOTTOM: 71.01,47.78 71.01,37.36 77.93,37.36 77.93,47.78

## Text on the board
BOTTOM: 170-29083 REV B | 9 OF 12 | L6_SS
Board Geometry/Soldermask Bottom: 10 OF 12 | SECONDARY SOLDERMASK
Package Geometry/Pastemask Bottom: SECONDARY SOLDERPASTE | 12 OF 12
Ref Des/Silkscreen Bottom: LP1 | LM1 | LP2 | CQ1 | CQ2 | LM2 | USB | CQ3 | LM3 | LP4 | CQ4 | LP3 | LM4 | 11 OF 12 | SECONDARY SILKSCREEN
User.Comments: CR_IOLINK_MASTER_1
TOP: 4 OF 12 | L1_PS
Board Geometry/Soldermask Top: 3 OF 12 | PRIMARY SOLDERMASK
Package Geometry/Pastemask Top: 1 OF 12 | PRIMARY SOLDERPASTE
Ref Des/Silkscreen Top: IO-LINK | MS1_1 | SPI0 | SPI1 | SPI | USB | EEPROM | SHU2 | DIS | SHUNT1 | LED4 | 3V3_SPI/USB | SHUNT4 | 24V | 3V3 | SHUNT3 | IO-LINK 4 | IO-LINK 3 | TWR_MISO | TWR_CLKI | TWR_CS | TWR_INT | TWR_MOSI | LED1 | LED2 | SHUNT2 | LED3 | RXD1 | TXEN1 | INTX | TXD1 | SSX | SDX1 | SCLK | RXD2 | MOSI | TXEN2 | MISO | TXD2 | GND | SDX2 | * | J72 PINS | 3-GND | 2-SCL | 1-SDA | LP2 | LP1 | LM1 | LM2 | MS1_2 | MS1 | MS2 | INT | TWR | CLK | CS0 | SWD | RST | LM3 | LM4 | LP4 | LP3 | CQ2 | CQ1 | CQ3 | CQ4 | 2 OF 12 | PRIMARY SILKSCREEN | TWR-CM3120-EVM | - | +
L2_PWR: 5 OF 12 | L2_PWR
L3_INT_1: 6 OF 12 | L3_INT_1
L4_INT_2: 7 OF 12 | L4_INT_2
L5_GND: 8 OF 12 | L5_GND
DIMENSION: GRID ORIGIN | PRIMARY DATUM | (2X) | (4X) | 16 | 22 | 8 | b. THE PCI CARD EDGE CONNECTOR GOLD FINGERS, PLATING REQUIREMENTS: | 30U OVER HARD GOLD OVER 100~200U NICKEL BOTH SIDES OF THE BOARD. | 17 | 7b | DETAIL C | VIEW FROM PRIMARY SIDE
User.6: [MM] | 06-15-16 | A.M. | B | RE-SPIN PER ECOXXX | 1
User.7: 5.00 | 4.25 | 4.50 | 90
User.8: FIGURE | SIZE | 8.0 | 8.1 | 28.0 | 40.0 | 41.0 | 47.0 | 48.0 | 63.0 | 35.0 | 81.0 | 110.0 | 63.0x52.0 | DRILL CHART: TOP to BOTTOM | ALL UNITS ARE IN MILS | TOLERANCE | +0.0/-8.0 | +2.0/-2.0 | +3.0/-3.0 | PLATED | NON-PLATED | QTY | 335 | 52 | 20 | 43 | 18 | 30 | 2 | 8 | 1
